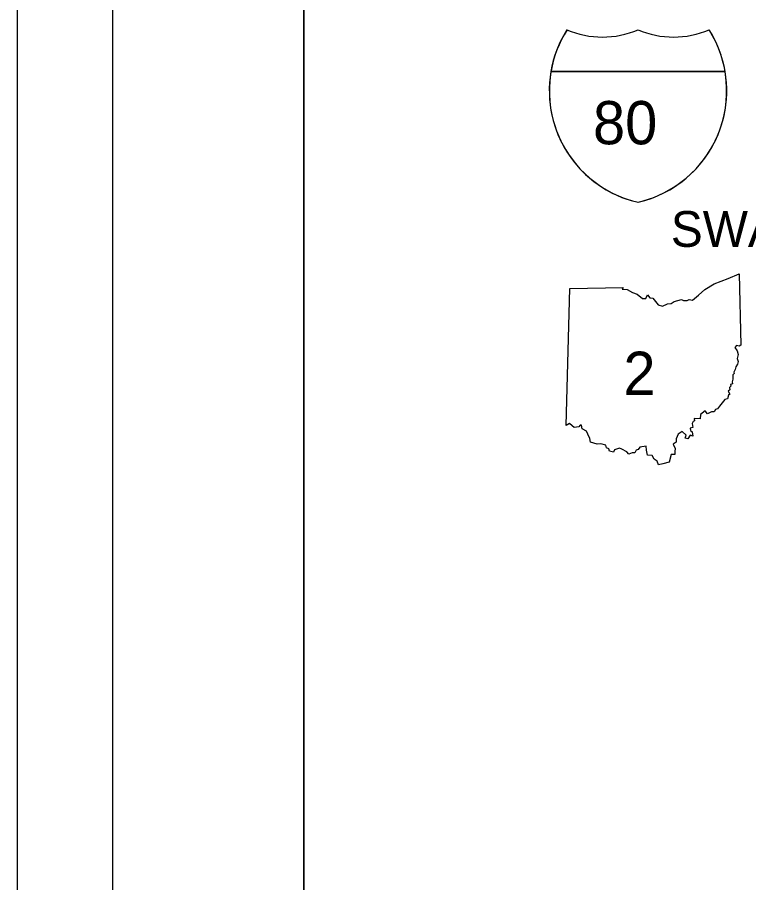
# Model space of a CAD drawing. Extents: x 0 to 750, y 0 to 507.
# Drawn here: x 0 to 76.6, y 149.3 to 239.9 of the extents above; entities that cross this region are included whole.
import ezdxf

# ---------------------------------------------------------------- set-up
doc = ezdxf.new("R2010")
doc.units = 0
for name, color, linetype in [('GM_X_Corporation_Text', 7, 'Continuous'), ('GM_X_Rail_Line', 7, 'Continuous'), ('SH_Border', 7, 'Continuous'), ('SH_Cut_Line', 7, 'Continuous')]:
    doc.layers.add(name, color=color, linetype=linetype)

msp = doc.modelspace()

# ---------------------------------------------------------------- linework, layer by layer
at = {"layer": 'GM_X_Rail_Line'}
for p, q in [((55.901, 234.263), (74.144, 234.263)), ((74.144, 234.263), (55.901, 234.263)), ((74.144, 234.263), (55.901, 234.263)), ((57.488, 197.194), (57.889, 211.556)), ((57.488, 197.194), (57.889, 211.556))]:
    msp.add_line(p, q, dxfattribs=at)
for points in [[(57.889, 211.556), (63.462, 211.65), (63.375, 211.476), (63.901, 211.44), (64.46, 211.133), (64.932, 210.939), (65.51, 210.483), (65.855, 210.488), (66.002, 210.862), (66.266, 210.573), (66.581, 210.522), (67.124, 209.834), (67.572, 209.685), (68.109, 209.921), (68.511, 209.96), (68.804, 210.192), (69.569, 210.392), (69.782, 210.272), (70.187, 210.296), (70.391, 210.385), (70.744, 210.306), (71.366, 210.828), (72.005, 211.444), (72.99, 212.025), (74.46, 212.575), (75.622, 213.068), (75.79, 205.614)], [(57.889, 211.556), (63.462, 211.65), (63.375, 211.476), (63.901, 211.44), (64.46, 211.133), (64.932, 210.939), (65.51, 210.483), (65.855, 210.488), (66.002, 210.862), (66.266, 210.573), (66.581, 210.522), (67.124, 209.834), (67.572, 209.685), (68.109, 209.921), (68.511, 209.96), (68.804, 210.192), (69.569, 210.392), (69.782, 210.272), (70.187, 210.296), (70.391, 210.385), (70.744, 210.306), (71.366, 210.828), (72.005, 211.444), (72.99, 212.025), (74.46, 212.575), (75.622, 213.068), (75.79, 205.614)], [(75.79, 205.614), (75.619, 205.51), (75.351, 205.559), (75.172, 205.35), (75.394, 205.001), (75.499, 204.632), (75.406, 204.226), (75.498, 203.891), (75.435, 203.611), (75.268, 203.332), (75.209, 203.066), (75.067, 202.786), (75.079, 202.629), (74.943, 202.504), (74.967, 202.038), (74.899, 201.78), (74.922, 201.557), (74.702, 201.499), (74.752, 201.315), (74.612, 201.172), (74.642, 200.928), (74.483, 200.772), (74.637, 200.459), (74.513, 200.36), (74.41, 199.979), (74.127, 199.902), (73.56, 199.207), (73.36, 198.944), (73.136, 198.878), (73.012, 198.608), (72.735, 198.607), (72.317, 198.42), (72.046, 198.742), (71.572, 198.354), (71.517, 197.907), (70.918, 197.921), (70.941, 197.694), (70.807, 197.628), (70.686, 197.402), (70.756, 196.999), (70.476, 196.896), (70.51, 196.662), (70.689, 196.519), (70.769, 196.071), (70.471, 196.162), (70.227, 195.785), (69.976, 195.874), (70.058, 196.193), (69.633, 196.577), (69.232, 196.269), (69.022, 195.778), (69.02, 195.447), (68.72, 195.247), (68.912, 194.78), (68.877, 194.459), (68.883, 194.153), (68.509, 194.164), (68.282, 193.339)], [(75.79, 205.614), (75.619, 205.51), (75.351, 205.559), (75.172, 205.35), (75.394, 205.001), (75.499, 204.632), (75.406, 204.226), (75.498, 203.891), (75.435, 203.611), (75.268, 203.332), (75.209, 203.066), (75.067, 202.786), (75.079, 202.629), (74.943, 202.504), (74.967, 202.038), (74.899, 201.78), (74.922, 201.557), (74.702, 201.499), (74.752, 201.315), (74.612, 201.172), (74.642, 200.928), (74.483, 200.772), (74.637, 200.459), (74.513, 200.36), (74.41, 199.979), (74.127, 199.902), (73.56, 199.207), (73.36, 198.944), (73.136, 198.878), (73.012, 198.608), (72.735, 198.607), (72.317, 198.42), (72.046, 198.742), (71.572, 198.354), (71.517, 197.907), (70.918, 197.921), (70.941, 197.694), (70.807, 197.628), (70.686, 197.402), (70.756, 196.999), (70.476, 196.896), (70.51, 196.662), (70.689, 196.519), (70.769, 196.071), (70.471, 196.162), (70.227, 195.785), (69.976, 195.874), (70.058, 196.193), (69.633, 196.577), (69.232, 196.269), (69.022, 195.778), (69.02, 195.447), (68.72, 195.247), (68.912, 194.78), (68.877, 194.459), (68.883, 194.153), (68.509, 194.164), (68.282, 193.339)], [(68.282, 193.339), (67.632, 193.182), (67.181, 193.087), (67.021, 193.462), (66.699, 193.659), (66.489, 194.036), (66.025, 194.088), (65.915, 194.606), (65.863, 195.026), (65.23, 194.922), (65.056, 194.665), (64.831, 194.596), (64.7, 194.337), (64.394, 194.316), (64.065, 194.194), (63.85, 194.447), (63.311, 194.703), (63.069, 194.834), (62.562, 194.63), (62.454, 194.388), (62.051, 194.495), (61.957, 194.764), (61.713, 194.845), (61.659, 195.131), (61.138, 195.284), (60.739, 195.223), (60.035, 195.453), (59.992, 195.83), (59.753, 196.288), (59.628, 196.607), (59.183, 196.85), (59.093, 197.229), (58.951, 197.217), (58.821, 197.064), (58.327, 196.993), (58.129, 197.148), (57.853, 197.412), (57.488, 197.194)], [(68.282, 193.339), (67.632, 193.182), (67.181, 193.087), (67.021, 193.462), (66.699, 193.659), (66.489, 194.036), (66.025, 194.088), (65.915, 194.606), (65.863, 195.026), (65.23, 194.922), (65.056, 194.665), (64.831, 194.596), (64.7, 194.337), (64.394, 194.316), (64.065, 194.194), (63.85, 194.447), (63.311, 194.703), (63.069, 194.834), (62.562, 194.63), (62.454, 194.388), (62.051, 194.495), (61.957, 194.764), (61.713, 194.845), (61.659, 195.131), (61.138, 195.284), (60.739, 195.223), (60.035, 195.453), (59.992, 195.83), (59.753, 196.288), (59.628, 196.607), (59.183, 196.85), (59.093, 197.229), (58.951, 197.217), (58.821, 197.064), (58.327, 196.993), (58.129, 197.148), (57.853, 197.412), (57.488, 197.194)]]:
    msp.add_lwpolyline(points, dxfattribs=at)
for centre, radius, start, end in [((67.721, 232.253), 11.99, 147.82161, 256.99413), ((66.971, 232.462), 11.216, 146.65397, 170.75899), ((61.298, 247.451), 9.567, 247.08482, 292.91053), ((61.298, 247.451), 9.567, 247.08482, 292.91053), ((62.324, 232.254), 11.989, 283.00654, 32.17868), ((68.747, 247.453), 9.569, 247.09162, 292.90836), ((68.747, 247.453), 9.569, 247.09162, 292.90836), ((62.324, 232.253), 11.99, 9.64753, 32.17902), ((67.72, 232.253), 11.989, 170.35136, 256.9967), ((62.349, 232.249), 11.966, 282.76665, 9.68983)]:
    msp.add_arc(centre, radius, start, end, dxfattribs=at)
at = {"layer": 'SH_Border'}
for points in [[(10, 430), (30, 430), (30, 10), (10, 10)], [(30, 430), (670, 430), (670, 10), (30, 10)]]:
    msp.add_lwpolyline(points, close=True, dxfattribs=at)
at = {"layer": 'SH_Cut_Line'}
msp.add_lwpolyline([(0, 0), (680, 0), (680, 440), (0, 440)], close=True, dxfattribs=at)

# ---------------------------------------------------------------- texts
at = {"layer": 'GM_X_Corporation_Text'}
msp.add_text('SWANTON', height=3.7501, rotation=0.00001, dxfattribs=at).set_placement((68.46, 215.906))
at = {"layer": 'GM_X_Rail_Line'}
for s, height, p in [('80', 4.5281, (60.305, 226.648)), ('2', 4.528, (63.49, 200.396))]:
    msp.add_text(s, height=height, dxfattribs=at).set_placement(p)

doc.saveas('drawing.dxf')
